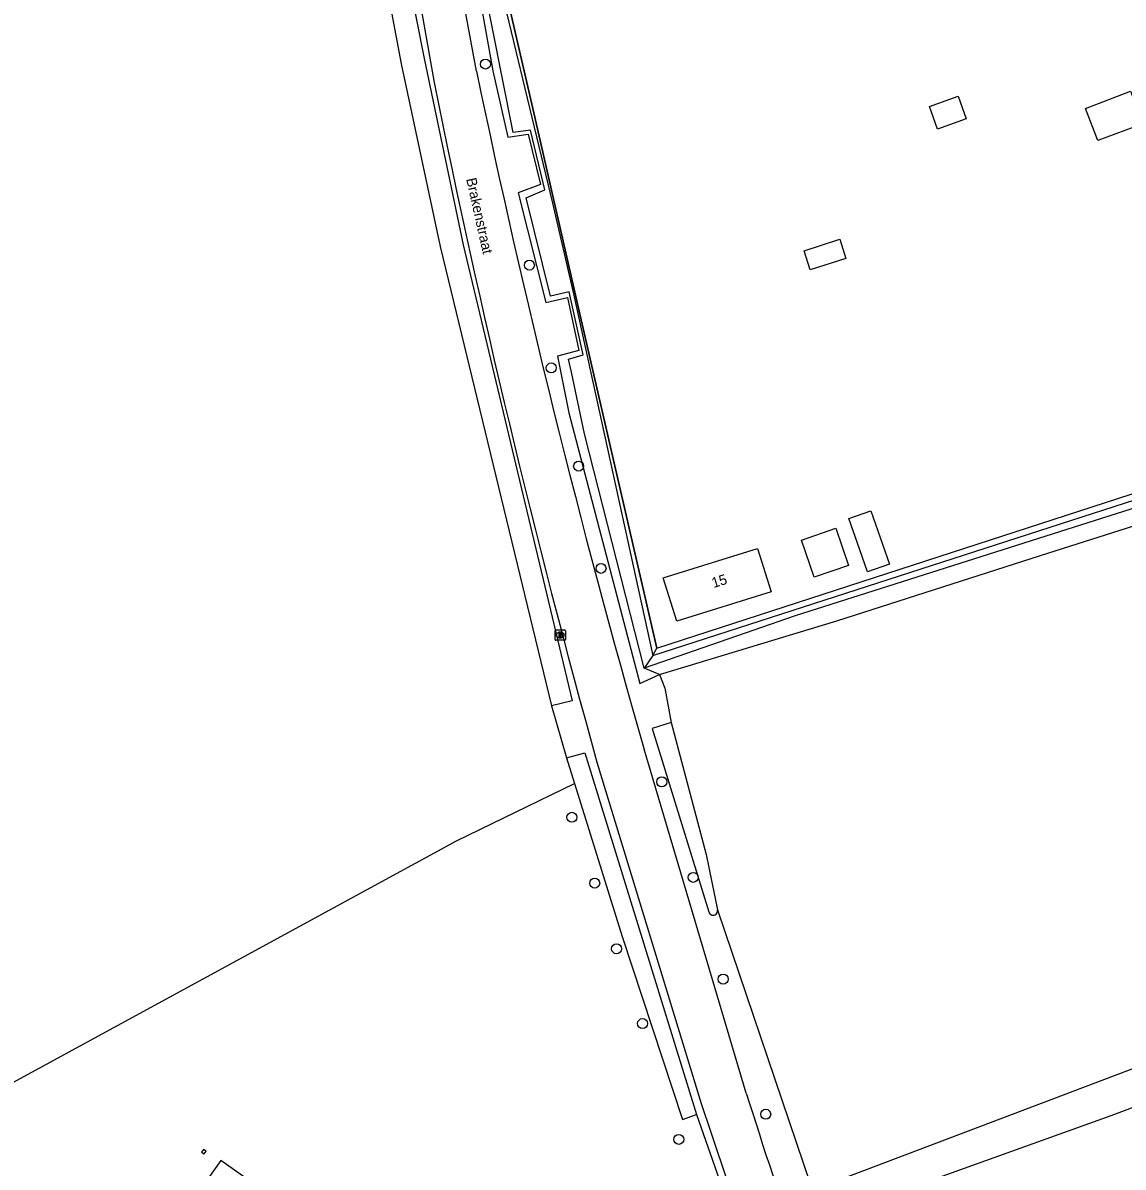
# Model space of a CAD drawing. Extents: x 163863 to 164644, y 379566 to 382155.
# Drawn here: x 164350.3 to 164457.9, y 381774.7 to 381886.6 of the extents above; entities that cross this region are included whole.
import ezdxf

# ---------------------------------------------------------------- set-up
doc = ezdxf.new("R2010")
doc.units = 0
for name, color, linetype in [('IMGEO_Boom', 7, 'Continuous'), ('IMGEO_Brandkraan', 7, 'Continuous'), ('IMGEO_Grasland_agrarisch', 7, 'Continuous'), ('IMGEO_Groenvoorziening', 7, 'Continuous'), ('IMGEO_Hek', 7, 'Continuous'), ('IMGEO_Oever', 7, 'Continuous'), ('IMGEO_Openbare_ruimte_label', 7, 'Continuous'), ('IMGEO_Pand', 7, 'Continuous'), ('IMGEO_Pand_nummerreeks', 7, 'Continuous'), ('IMGEO_Rijbaan_lokaal_halfverhard', 7, 'Continuous'), ('IMGEO_Waterloop', 7, 'Continuous')]:
    doc.layers.add(name, color=color, linetype=linetype)

msp = doc.modelspace()

# ---------------------------------------------------------------- linework, layer by layer
at = {"layer": 'IMGEO_Boom'}
for centre in [(164395.55, 381882.56), (164399.85, 381862.9), (164401.99, 381852.85), (164404.67, 381843.25), (164406.86, 381833.25), (164412.8, 381812.38), (164404.01, 381808.91), (164415.88, 381803.04), (164406.24, 381802.48), (164408.38, 381796.06), (164418.81, 381793.09), (164410.92, 381788.74), (164422.97, 381779.88), (164414.46, 381777.42)]:
    msp.add_circle(centre, 0.489, dxfattribs=at)
at = {"layer": 'IMGEO_Brandkraan'}
for p, q in [((164402.37, 381826.3), (164402.37, 381827.15)), ((164402.44, 381827.23), (164403.3, 381827.23)), ((164402.86, 381827.01), (164402.88, 381827.01)), ((164403.37, 381827.15), (164403.37, 381826.3)), ((164403.3, 381826.23), (164402.44, 381826.23)), ((164402.88, 381826.45), (164402.85, 381826.45))]:
    msp.add_line(p, q, dxfattribs=at)
for points in [[(164402.37, 381826.3), (164402.37, 381827.15)], [(164402.44, 381827.23), (164403.3, 381827.23)], [(164402.72, 381826.93), (164402.72, 381826.53), (164402.93, 381826.53)], [(164402.95, 381826.93), (164402.72, 381826.93)], [(164402.89, 381826.85), (164402.84, 381826.85), (164402.84, 381826.77)], [(164403.37, 381827.15), (164403.37, 381826.3)], [(164403.3, 381826.23), (164402.44, 381826.23)], [(164402.84, 381826.77), (164402.89, 381826.77)], [(164402.9, 381826.69), (164402.84, 381826.69), (164402.84, 381826.61)], [(164402.84, 381826.61), (164402.9, 381826.61)]]:
    msp.add_lwpolyline(points, dxfattribs=at)
for centre, radius, start, end in [((164402.44, 381827.15), 0.0765, 91.552, 178.448), ((164402.44, 381827.15), 0.0765, 91.552, 178.448), ((164402.9, 381826.81), 0.0379, 267.8285, 90.9355), ((164402.95, 381826.78), 0.145, 59.4692, 91.5367), ((164402.98, 381826.83), 0.0922, 285.5137, 58.1501), ((164403.29, 381827.15), 0.0765, 1.552, 88.448), ((164403.29, 381827.15), 0.0765, 1.552, 88.448), ((164402.44, 381826.3), 0.0765, 181.552, 268.448), ((164402.44, 381826.3), 0.0765, 181.552, 268.448), ((164402.9, 381826.65), 0.0404, 269.8759, 90.5077), ((164402.93, 381826.78), 0.251, 268.6676, 293.5347), ((164402.98, 381826.64), 0.105, 301.3115, 78.989), ((164403.29, 381826.3), 0.0765, 271.552, 358.448), ((164403.29, 381826.3), 0.0765, 271.552, 358.448)]:
    msp.add_arc(centre, radius, start, end, dxfattribs=at)
for centre, major_axis, ratio, start_param, end_param in [((164402.86, 381826.73), (-0.387, 0.002), 0.722429, 4.712389, 7.853982), ((164402.88, 381826.73), (-0.39, 0.002), 0.717154, 1.570796, 4.712389)]:
    msp.add_ellipse(centre, major_axis=major_axis, ratio=ratio, start_param=start_param, end_param=end_param, dxfattribs=at)
at = {"layer": 'IMGEO_Grasland_agrarisch'}
for points in [[(164412.59, 381822.86), (164429.92, 381828.12), (164449.86, 381834.52), (164497.51, 381849.65), (164537.18, 381862.49), (164575.73, 381874.87), (164599.26, 381882.52)], [(164600.1, 381839.01), (164585.23, 381833.12), (164548.83, 381818.75), (164518.64, 381806.88), (164490.64, 381796.47), (164469.45, 381788.32), (164427.55, 381772.44)], [(164412.59, 381822.86), (164413.11, 381821.55), (164413.73, 381818.17)], [(164402.01, 381819.81), (164403.47, 381814.73)], [(164335.01, 381775.05), (164338.75, 381777.23), (164392.73, 381806.6), (164404.25, 381812.22)], [(164443.54, 381737.47), (164442.94, 381737.25), (164436.97, 381753.01), (164430.96, 381770.51), (164456.78, 381779.76), (164478.35, 381787.87), (164505.55, 381798.32), (164526.66, 381806.51), (164530.39, 381805.09), (164531.54, 381804.48), (164532.49, 381803.4), (164538.3, 381784.94), (164539.44, 381780.67), (164539.19, 381777.89), (164537.82, 381775.6), (164535.89, 381774.09), (164533.83, 381772.76), (164490.02, 381755.43), (164443.54, 381737.47)], [(164418.25, 381799.85), (164427.35, 381773.02), (164427.55, 381772.44)]]:
    msp.add_lwpolyline(points, dxfattribs=at)
at = {"layer": 'IMGEO_Groenvoorziening'}
for points in [[(164598.04, 381945.02), (164500, 381920.51), (164396.41, 381894.6), (164400.28, 381877.79), (164404.82, 381857.96), (164412.31, 381825.45)], [(164393.58, 381896.98), (164396.26, 381881.9), (164397.74, 381875.4), (164399.72, 381875.7), (164400.94, 381870.79), (164398.75, 381869.96), (164401.45, 381859.25), (164403.57, 381859.74), (164404.68, 381854.55), (164402.59, 381853.99), (164403.71, 381848.45), (164410.64, 381821.98), (164412.59, 381822.86)], [(164412.31, 381825.45), (164500, 381853.89), (164599.19, 381886.07)], [(164416.2, 381779.85), (164421.55, 381764.61)]]:
    msp.add_lwpolyline(points, dxfattribs=at)
at = {"layer": 'IMGEO_Hek'}
for points in [[(164412.31, 381825.45), (164404.82, 381857.96), (164400.28, 381877.79), (164396.41, 381894.6)], [(164412.31, 381825.45), (164500, 381853.89), (164599.19, 381886.07)]]:
    msp.add_lwpolyline(points, dxfattribs=at)
at = {"layer": 'IMGEO_Oever'}
for points in [[(164411.92, 381824.73), (164412.31, 381825.45)], [(164412.59, 381822.86), (164411.07, 381823.48)]]:
    msp.add_lwpolyline(points, dxfattribs=at)
at = {"layer": 'IMGEO_Pand'}
for points in [[(164442.58, 381877.19), (164439.77, 381876.2), (164438.99, 381878.42), (164441.8, 381879.41), (164442.58, 381877.19)], [(164459.85, 381876.73), (164455.45, 381875.07), (164454.25, 381878.23), (164458.66, 381879.9), (164459.85, 381876.73)], [(164430.82, 381863.55), (164427.33, 381862.43), (164426.73, 381864.31), (164430.22, 381865.43), (164430.82, 381863.55)], [(164435.08, 381833.66), (164432.94, 381832.91), (164431.96, 381835.7), (164431.11, 381838.11), (164433.24, 381838.86), (164435.08, 381833.66)], [(164431.08, 381833.54), (164427.72, 381832.39), (164426.47, 381836.02), (164429.83, 381837.17), (164431.08, 381833.54)], [(164422.18, 381835.18), (164423.49, 381830.94), (164414.26, 381828.09), (164412.95, 381832.33), (164422.18, 381835.18)], [(164368.03, 381776), (164368.22, 381776.26), (164367.96, 381776.44), (164367.77, 381776.18), (164368.03, 381776)], [(164363.4, 381766.51), (164360.43, 381762.3), (164364.99, 381759.08), (164374.23, 381772.12), (164369.66, 381775.36), (164363.4, 381766.51)]]:
    msp.add_lwpolyline(points, dxfattribs=at)
at = {"layer": 'IMGEO_Rijbaan_lokaal_halfverhard'}
for points in [[(164394.68, 381881.88), (164388.1, 381917.44), (164387.74, 381919.59), (164379.47, 381969.66), (164377.03, 381983.08), (164376.33, 381987.84), (164375.07, 382000), (164368.33, 382065.24), (164366.23, 382081.36), (164364.66, 382091.74), (164362.19, 382105.09)], [(164360.43, 382089.08), (164361.43, 382082.09), (164365.91, 382044.84), (164370.62, 382000), (164372.7, 381981.96), (164377.52, 381953.78), (164381.31, 381930.61), (164383.71, 381918.93), (164384.14, 381916.84), (164390.52, 381880.76)], [(164421.07, 381781.95), (164411.08, 381815.56)], [(164406.46, 381814.29), (164416.64, 381780.93)]]:
    msp.add_lwpolyline(points, dxfattribs=at)
for centre, radius, start, end in [((165292.34, 382068.69), 916.9, 191.75614, 196.0263), ((165324.24, 382069.52), 952.61, 191.4287, 195.54119), ((165706.5, 382210.95), 1359.65, 198.43767, 199.81713), ((165106.27, 381998.23), 718.53, 197.51825, 200.2104)]:
    msp.add_arc(centre, radius, start, end, dxfattribs=at)
at = {"layer": 'IMGEO_Waterloop'}
for points in [[(164381.64, 381916.11), (164383.28, 381916.29), (164385.41, 381903.99), (164389.55, 381883.1), (164393.37, 381864.87), (164404.05, 381820.29), (164402.01, 381819.81)], [(164381.64, 381916.11), (164383.56, 381902.54), (164387.32, 381882.58), (164391.12, 381864.73), (164402.01, 381819.81)], [(164411.07, 381823.48), (164405.25, 381846.41), (164403.98, 381852.44), (164403.68, 381853.71), (164405.1, 381854.12), (164403.74, 381860.3), (164401.92, 381859.87), (164399.54, 381869.47), (164401.36, 381870.27), (164399.96, 381876.09), (164398.26, 381875.88), (164394.19, 381896.39)], [(164395.83, 381895.07), (164402.11, 381868.95), (164404.15, 381860.08), (164411.92, 381824.73)], [(164411.92, 381824.73), (164525.3, 381861.33), (164597.65, 381884.75), (164599.21, 381885.24)], [(164599.24, 381883.67), (164597.82, 381883.23), (164425.84, 381828.62), (164411.07, 381823.48)], [(164411.92, 381824.73), (164411.07, 381823.48)], [(164413.73, 381818.17), (164411.85, 381817.58), (164417.42, 381799.68)], [(164413.73, 381818.17), (164417.16, 381805.27), (164418.25, 381799.85)], [(164403.47, 381814.73), (164405.26, 381815.2), (164416.2, 381779.85)], [(164403.47, 381814.73), (164404.25, 381812.22)], [(164404.25, 381812.22), (164408.91, 381797.24), (164414.83, 381779.35), (164416.2, 381779.85)]]:
    msp.add_lwpolyline(points, dxfattribs=at)
msp.add_arc((164417.84, 381799.75), 0.425, 188.4757, 14.7527, dxfattribs=at)

# ---------------------------------------------------------------- texts
at = {"layer": 'IMGEO_Openbare_ruimte_label'}
msp.add_text('Brakenstraat', height=1, rotation=282.591, dxfattribs=at).set_placement((164393.66, 381871.32))
at = {"layer": 'IMGEO_Pand_nummerreeks'}
msp.add_text('15', height=1, rotation=17.1314, dxfattribs=at).set_placement((164417.86, 381831.32))

doc.saveas('drawing.dxf')
